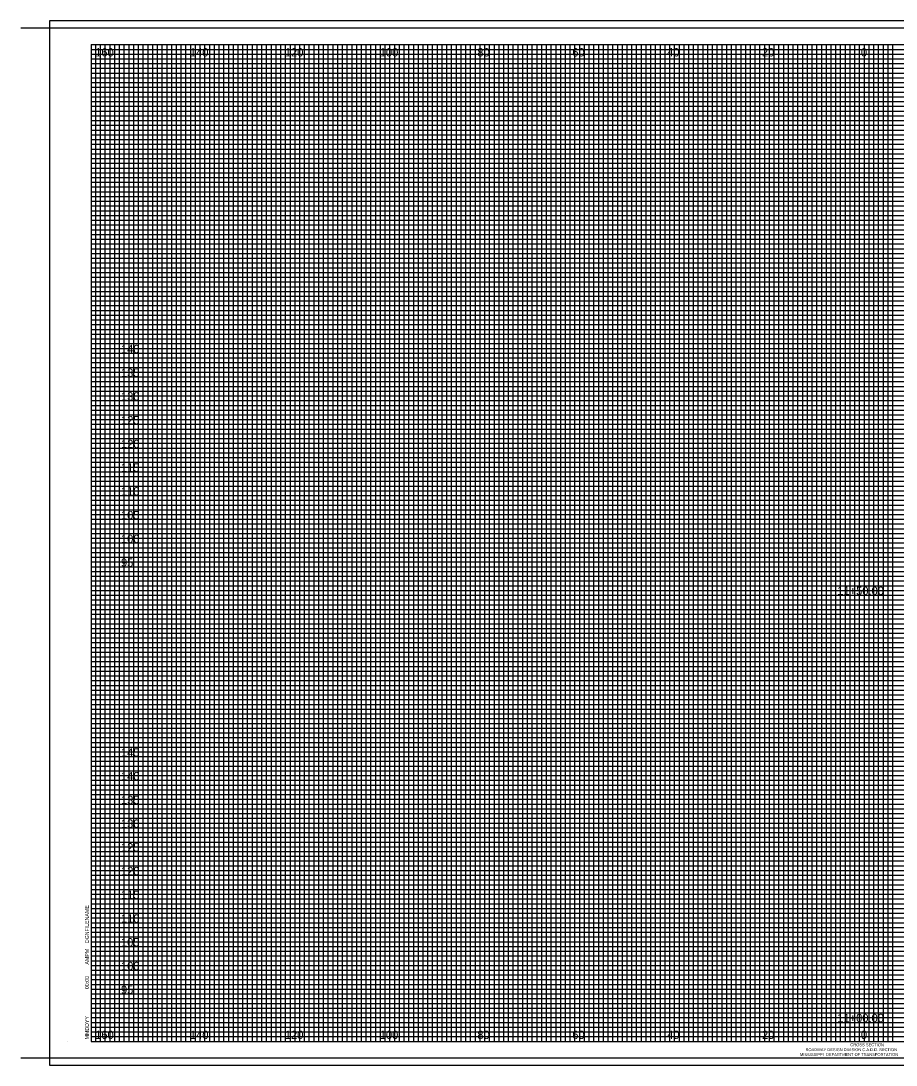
# Model space of a CAD drawing. Extents: x 21281 to 21817, y 6470 to 8300.
# Drawn here: x 21465 to 21649.5, y 6699.8 to 6919.8 of the extents above; entities that cross this region are included whole.
import ezdxf

# ---------------------------------------------------------------- set-up
doc = ezdxf.new("R2010")
doc.units = 0
for name, color, linetype in [('SHEET_BORDER', 7, 'Continuous'), ('SHEET_BORDER_TX', 7, 'Continuous'), ('SHEET_DATE_DGN_TX', 7, 'Continuous'), ('SHEET_PLOTTING_SHAPE', 7, 'Continuous'), ('XS_SHEET_LABELS_ELEVATION', 7, 'Continuous'), ('XS_SHEET_LABELS_OFFSET', 7, 'Continuous'), ('XS_SHEET_LABELS_STATION', 7, 'Continuous'), ('XS_SHEET_MAJOR_GRIDS', 7, 'Continuous'), ('XS_SHEET_MEDIUM_GRIDS', 7, 'Continuous'), ('XS_SHEET_MINOR_GRIDS', 7, 'Continuous')]:
    doc.layers.add(name, color=color, linetype=linetype)

msp = doc.modelspace()

# ---------------------------------------------------------------- linework, layer by layer
at = {"layer": 'SHEET_BORDER'}
for p, q in [((21465.04, 6918.34), (21817.04, 6918.34)), ((21479.84, 6914.84), (21814.84, 6914.84)), ((21479.84, 6914.84), (21479.84, 6704.84)), ((21623.84, 6704.84), (21623.84, 6914.84)), ((21474.84, 6704.84), (21474.84, 6704.84)), ((21479.84, 6704.84), (21814.84, 6704.84)), ((21465.04, 6701.34), (21817.04, 6701.34))]:
    msp.add_line(p, q, dxfattribs=at)
at = {"layer": 'SHEET_PLOTTING_SHAPE'}
msp.add_lwpolyline([(21471.04, 6699.84), (21817.04, 6699.84), (21817.04, 6919.84), (21471.04, 6919.84)], close=True, dxfattribs=at)
at = {"layer": 'XS_SHEET_MAJOR_GRIDS'}
for p, q in [((21484.84, 6704.84), (21484.84, 6914.84)), ((21494.84, 6704.84), (21494.84, 6914.84)), ((21504.84, 6704.84), (21504.84, 6914.84)), ((21514.84, 6704.84), (21514.84, 6914.84)), ((21524.84, 6704.84), (21524.84, 6914.84)), ((21534.84, 6704.84), (21534.84, 6914.84)), ((21544.84, 6704.84), (21544.84, 6914.84)), ((21554.84, 6704.84), (21554.84, 6914.84)), ((21564.84, 6704.84), (21564.84, 6914.84)), ((21574.84, 6704.84), (21574.84, 6914.84)), ((21584.84, 6704.84), (21584.84, 6914.84)), ((21594.84, 6704.84), (21594.84, 6914.84)), ((21604.84, 6704.84), (21604.84, 6914.84)), ((21614.84, 6704.84), (21614.84, 6914.84)), ((21624.84, 6704.84), (21624.84, 6914.84)), ((21634.84, 6704.84), (21634.84, 6914.84)), ((21644.84, 6704.84), (21644.84, 6914.84)), ((21479.84, 6904.84), (21814.84, 6904.84)), ((21479.84, 6894.84), (21814.84, 6894.84)), ((21479.84, 6884.84), (21814.84, 6884.84)), ((21479.84, 6874.84), (21814.84, 6874.84)), ((21479.84, 6864.84), (21814.84, 6864.84)), ((21479.84, 6854.84), (21814.84, 6854.84)), ((21479.84, 6844.84), (21814.84, 6844.84)), ((21479.84, 6834.84), (21814.84, 6834.84)), ((21479.84, 6824.84), (21814.84, 6824.84)), ((21479.84, 6814.84), (21814.84, 6814.84)), ((21479.84, 6804.84), (21814.84, 6804.84)), ((21479.84, 6794.84), (21814.84, 6794.84)), ((21479.84, 6784.84), (21814.84, 6784.84)), ((21479.84, 6774.84), (21814.84, 6774.84)), ((21479.84, 6764.84), (21814.84, 6764.84)), ((21479.84, 6754.84), (21814.84, 6754.84)), ((21479.84, 6744.84), (21814.84, 6744.84)), ((21479.84, 6734.84), (21814.84, 6734.84)), ((21479.84, 6724.84), (21814.84, 6724.84)), ((21479.84, 6714.84), (21814.84, 6714.84))]:
    msp.add_line(p, q, dxfattribs=at)
at = {"layer": 'XS_SHEET_MEDIUM_GRIDS'}
for p, q in [((21489.84, 6704.84), (21489.84, 6914.84)), ((21499.84, 6704.84), (21499.84, 6914.84)), ((21509.84, 6704.84), (21509.84, 6914.84)), ((21519.84, 6704.84), (21519.84, 6914.84)), ((21529.84, 6704.84), (21529.84, 6914.84)), ((21539.84, 6704.84), (21539.84, 6914.84)), ((21549.84, 6704.84), (21549.84, 6914.84)), ((21559.84, 6704.84), (21559.84, 6914.84)), ((21569.84, 6704.84), (21569.84, 6914.84)), ((21579.84, 6704.84), (21579.84, 6914.84)), ((21589.84, 6704.84), (21589.84, 6914.84)), ((21599.84, 6704.84), (21599.84, 6914.84)), ((21609.84, 6704.84), (21609.84, 6914.84)), ((21619.84, 6704.84), (21619.84, 6914.84)), ((21629.84, 6704.84), (21629.84, 6914.84)), ((21639.84, 6704.84), (21639.84, 6914.84)), ((21479.84, 6909.84), (21787.84, 6909.84)), ((21479.84, 6899.84), (21814.84, 6899.84)), ((21479.84, 6889.84), (21814.84, 6889.84)), ((21479.84, 6879.84), (21814.84, 6879.84)), ((21479.84, 6869.84), (21814.84, 6869.84)), ((21479.84, 6859.84), (21814.84, 6859.84)), ((21479.84, 6849.84), (21814.84, 6849.84)), ((21479.84, 6839.84), (21814.84, 6839.84)), ((21479.84, 6829.84), (21814.84, 6829.84)), ((21479.84, 6819.84), (21814.84, 6819.84)), ((21479.84, 6809.84), (21814.84, 6809.84)), ((21479.84, 6799.84), (21814.84, 6799.84)), ((21479.84, 6789.84), (21814.84, 6789.84)), ((21479.84, 6779.84), (21814.84, 6779.84)), ((21479.84, 6769.84), (21814.84, 6769.84)), ((21479.84, 6759.84), (21814.84, 6759.84)), ((21479.84, 6749.84), (21814.84, 6749.84)), ((21479.84, 6739.84), (21814.84, 6739.84)), ((21479.84, 6729.84), (21814.84, 6729.84)), ((21479.84, 6719.84), (21814.84, 6719.84)), ((21479.84, 6709.84), (21804.84, 6709.84))]:
    msp.add_line(p, q, dxfattribs=at)
at = {"layer": 'XS_SHEET_MINOR_GRIDS'}
for p, q in [((21480.84, 6704.84), (21480.84, 6914.84)), ((21481.84, 6704.84), (21481.84, 6914.84)), ((21482.84, 6704.84), (21482.84, 6914.84)), ((21483.84, 6704.84), (21483.84, 6914.84)), ((21485.84, 6704.84), (21485.84, 6914.84)), ((21486.84, 6704.84), (21486.84, 6914.84)), ((21487.84, 6704.84), (21487.84, 6914.84)), ((21488.84, 6704.84), (21488.84, 6914.84)), ((21490.84, 6704.84), (21490.84, 6914.84)), ((21491.84, 6704.84), (21491.84, 6914.84)), ((21492.84, 6704.84), (21492.84, 6914.84)), ((21493.84, 6704.84), (21493.84, 6914.84)), ((21495.84, 6704.84), (21495.84, 6914.84)), ((21496.84, 6704.84), (21496.84, 6914.84)), ((21497.84, 6704.84), (21497.84, 6914.84)), ((21498.84, 6704.84), (21498.84, 6914.84)), ((21500.84, 6704.84), (21500.84, 6914.84)), ((21501.84, 6704.84), (21501.84, 6914.84)), ((21502.84, 6704.84), (21502.84, 6914.84)), ((21503.84, 6704.84), (21503.84, 6914.84)), ((21505.84, 6704.84), (21505.84, 6914.84)), ((21506.84, 6704.84), (21506.84, 6914.84)), ((21507.84, 6704.84), (21507.84, 6914.84)), ((21508.84, 6704.84), (21508.84, 6914.84)), ((21510.84, 6704.84), (21510.84, 6914.84)), ((21511.84, 6704.84), (21511.84, 6914.84)), ((21512.84, 6704.84), (21512.84, 6914.84)), ((21513.84, 6704.84), (21513.84, 6914.84)), ((21515.84, 6704.84), (21515.84, 6914.84)), ((21516.84, 6704.84), (21516.84, 6914.84)), ((21517.84, 6704.84), (21517.84, 6914.84)), ((21518.84, 6704.84), (21518.84, 6914.84)), ((21520.84, 6704.84), (21520.84, 6914.84)), ((21521.84, 6704.84), (21521.84, 6914.84)), ((21522.84, 6704.84), (21522.84, 6914.84)), ((21523.84, 6704.84), (21523.84, 6914.84)), ((21525.84, 6704.84), (21525.84, 6914.84)), ((21526.84, 6704.84), (21526.84, 6914.84)), ((21527.84, 6704.84), (21527.84, 6914.84)), ((21528.84, 6704.84), (21528.84, 6914.84)), ((21530.84, 6704.84), (21530.84, 6914.84)), ((21531.84, 6704.84), (21531.84, 6914.84)), ((21532.84, 6704.84), (21532.84, 6914.84)), ((21533.84, 6704.84), (21533.84, 6914.84)), ((21535.84, 6704.84), (21535.84, 6914.84)), ((21536.84, 6704.84), (21536.84, 6914.84)), ((21537.84, 6704.84), (21537.84, 6914.84)), ((21538.84, 6704.84), (21538.84, 6914.84)), ((21540.84, 6704.84), (21540.84, 6914.84)), ((21541.84, 6704.84), (21541.84, 6914.84)), ((21542.84, 6704.84), (21542.84, 6914.84)), ((21543.84, 6704.84), (21543.84, 6914.84)), ((21545.84, 6704.84), (21545.84, 6914.84)), ((21546.84, 6704.84), (21546.84, 6914.84)), ((21547.84, 6704.84), (21547.84, 6914.84)), ((21548.84, 6704.84), (21548.84, 6914.84)), ((21550.84, 6704.84), (21550.84, 6914.84)), ((21551.84, 6704.84), (21551.84, 6914.84)), ((21552.84, 6704.84), (21552.84, 6914.84)), ((21553.84, 6704.84), (21553.84, 6914.84)), ((21555.84, 6704.84), (21555.84, 6914.84)), ((21556.84, 6704.84), (21556.84, 6914.84)), ((21557.84, 6704.84), (21557.84, 6914.84)), ((21558.84, 6704.84), (21558.84, 6914.84)), ((21560.84, 6704.84), (21560.84, 6914.84)), ((21561.84, 6704.84), (21561.84, 6914.84)), ((21562.84, 6704.84), (21562.84, 6914.84)), ((21563.84, 6704.84), (21563.84, 6914.84)), ((21565.84, 6704.84), (21565.84, 6914.84)), ((21566.84, 6704.84), (21566.84, 6914.84)), ((21567.84, 6704.84), (21567.84, 6914.84)), ((21568.84, 6704.84), (21568.84, 6914.84)), ((21570.84, 6704.84), (21570.84, 6914.84)), ((21571.84, 6704.84), (21571.84, 6914.84)), ((21572.84, 6704.84), (21572.84, 6914.84)), ((21573.84, 6704.84), (21573.84, 6914.84)), ((21575.84, 6704.84), (21575.84, 6914.84)), ((21576.84, 6704.84), (21576.84, 6914.84)), ((21577.84, 6704.84), (21577.84, 6914.84)), ((21578.84, 6704.84), (21578.84, 6914.84)), ((21580.84, 6704.84), (21580.84, 6914.84)), ((21581.84, 6704.84), (21581.84, 6914.84)), ((21582.84, 6704.84), (21582.84, 6914.84)), ((21583.84, 6704.84), (21583.84, 6914.84)), ((21585.84, 6704.84), (21585.84, 6914.84)), ((21586.84, 6704.84), (21586.84, 6914.84)), ((21587.84, 6704.84), (21587.84, 6914.84)), ((21588.84, 6704.84), (21588.84, 6914.84)), ((21590.84, 6704.84), (21590.84, 6914.84)), ((21591.84, 6704.84), (21591.84, 6914.84)), ((21592.84, 6704.84), (21592.84, 6914.84)), ((21593.84, 6704.84), (21593.84, 6914.84)), ((21595.84, 6704.84), (21595.84, 6914.84)), ((21596.84, 6704.84), (21596.84, 6914.84)), ((21597.84, 6704.84), (21597.84, 6914.84)), ((21598.84, 6704.84), (21598.84, 6914.84)), ((21600.84, 6704.84), (21600.84, 6914.84)), ((21601.84, 6704.84), (21601.84, 6914.84)), ((21602.84, 6704.84), (21602.84, 6914.84)), ((21603.84, 6704.84), (21603.84, 6914.84)), ((21605.84, 6704.84), (21605.84, 6914.84)), ((21606.84, 6704.84), (21606.84, 6914.84)), ((21607.84, 6704.84), (21607.84, 6914.84)), ((21608.84, 6704.84), (21608.84, 6914.84)), ((21610.84, 6704.84), (21610.84, 6914.84)), ((21611.84, 6704.84), (21611.84, 6914.84)), ((21612.84, 6704.84), (21612.84, 6914.84)), ((21613.84, 6704.84), (21613.84, 6914.84)), ((21615.84, 6704.84), (21615.84, 6914.84)), ((21616.84, 6704.84), (21616.84, 6914.84)), ((21617.84, 6704.84), (21617.84, 6914.84)), ((21618.84, 6704.84), (21618.84, 6914.84)), ((21620.84, 6704.84), (21620.84, 6914.84)), ((21621.84, 6704.84), (21621.84, 6914.84)), ((21622.84, 6704.84), (21622.84, 6914.84)), ((21625.84, 6704.84), (21625.84, 6914.84)), ((21626.84, 6704.84), (21626.84, 6914.84)), ((21627.84, 6704.84), (21627.84, 6914.84)), ((21628.84, 6704.84), (21628.84, 6914.84)), ((21630.84, 6704.84), (21630.84, 6914.84)), ((21631.84, 6704.84), (21631.84, 6914.84)), ((21632.84, 6704.84), (21632.84, 6914.84)), ((21633.84, 6704.84), (21633.84, 6914.84)), ((21635.84, 6704.84), (21635.84, 6914.84)), ((21636.84, 6704.84), (21636.84, 6914.84)), ((21637.84, 6704.84), (21637.84, 6914.84)), ((21638.84, 6704.84), (21638.84, 6914.84)), ((21640.84, 6704.84), (21640.84, 6914.84)), ((21641.84, 6704.84), (21641.84, 6914.84)), ((21642.84, 6704.84), (21642.84, 6914.84)), ((21643.84, 6704.84), (21643.84, 6914.84)), ((21645.84, 6704.84), (21645.84, 6914.84)), ((21646.84, 6704.84), (21646.84, 6914.84)), ((21647.84, 6704.84), (21647.84, 6914.84)), ((21648.84, 6704.84), (21648.84, 6914.84)), ((21479.84, 6913.84), (21787.84, 6913.84)), ((21479.84, 6912.84), (21787.84, 6912.84)), ((21479.84, 6911.84), (21787.84, 6911.84)), ((21479.84, 6910.84), (21787.84, 6910.84)), ((21479.84, 6908.84), (21787.84, 6908.84)), ((21479.84, 6907.84), (21787.84, 6907.84)), ((21479.84, 6906.84), (21787.84, 6906.84)), ((21479.84, 6905.84), (21814.84, 6905.84)), ((21479.84, 6903.84), (21814.84, 6903.84)), ((21479.84, 6902.84), (21814.84, 6902.84)), ((21479.84, 6901.84), (21814.84, 6901.84)), ((21479.84, 6900.84), (21814.84, 6900.84)), ((21479.84, 6898.84), (21814.84, 6898.84)), ((21479.84, 6897.84), (21814.84, 6897.84)), ((21479.84, 6896.84), (21814.84, 6896.84)), ((21479.84, 6895.84), (21814.84, 6895.84)), ((21479.84, 6893.84), (21814.84, 6893.84)), ((21479.84, 6892.84), (21814.84, 6892.84)), ((21479.84, 6891.84), (21814.84, 6891.84)), ((21479.84, 6890.84), (21814.84, 6890.84)), ((21479.84, 6888.84), (21814.84, 6888.84)), ((21479.84, 6887.84), (21814.84, 6887.84)), ((21479.84, 6886.84), (21814.84, 6886.84)), ((21479.84, 6885.84), (21814.84, 6885.84)), ((21479.84, 6883.84), (21814.84, 6883.84)), ((21479.84, 6882.84), (21814.84, 6882.84)), ((21479.84, 6881.84), (21814.84, 6881.84)), ((21479.84, 6880.84), (21814.84, 6880.84)), ((21479.84, 6878.84), (21814.84, 6878.84)), ((21479.84, 6877.84), (21814.84, 6877.84)), ((21479.84, 6876.84), (21814.84, 6876.84)), ((21479.84, 6875.84), (21814.84, 6875.84)), ((21479.84, 6873.84), (21814.84, 6873.84)), ((21479.84, 6872.84), (21814.84, 6872.84)), ((21479.84, 6871.84), (21814.84, 6871.84)), ((21479.84, 6870.84), (21814.84, 6870.84)), ((21479.84, 6868.84), (21814.84, 6868.84)), ((21479.84, 6867.84), (21814.84, 6867.84)), ((21479.84, 6866.84), (21814.84, 6866.84)), ((21479.84, 6865.84), (21814.84, 6865.84)), ((21479.84, 6863.84), (21814.84, 6863.84)), ((21479.84, 6862.84), (21814.84, 6862.84)), ((21479.84, 6861.84), (21814.84, 6861.84)), ((21479.84, 6860.84), (21814.84, 6860.84)), ((21479.84, 6858.84), (21814.84, 6858.84)), ((21479.84, 6857.84), (21814.84, 6857.84)), ((21479.84, 6856.84), (21814.84, 6856.84)), ((21479.84, 6855.84), (21814.84, 6855.84)), ((21479.84, 6853.84), (21814.84, 6853.84)), ((21479.84, 6852.84), (21814.84, 6852.84)), ((21479.84, 6851.84), (21814.84, 6851.84)), ((21479.84, 6850.84), (21814.84, 6850.84)), ((21479.84, 6848.84), (21814.84, 6848.84)), ((21479.84, 6847.84), (21814.84, 6847.84)), ((21479.84, 6846.84), (21814.84, 6846.84)), ((21479.84, 6845.84), (21814.84, 6845.84)), ((21479.84, 6843.84), (21814.84, 6843.84)), ((21479.84, 6842.84), (21814.84, 6842.84)), ((21479.84, 6841.84), (21814.84, 6841.84)), ((21479.84, 6840.84), (21814.84, 6840.84)), ((21479.84, 6838.84), (21814.84, 6838.84)), ((21479.84, 6837.84), (21814.84, 6837.84)), ((21479.84, 6836.84), (21814.84, 6836.84)), ((21479.84, 6835.84), (21814.84, 6835.84)), ((21479.84, 6833.84), (21814.84, 6833.84)), ((21479.84, 6832.84), (21814.84, 6832.84)), ((21479.84, 6831.84), (21814.84, 6831.84)), ((21479.84, 6830.84), (21814.84, 6830.84)), ((21479.84, 6828.84), (21814.84, 6828.84)), ((21479.84, 6827.84), (21814.84, 6827.84)), ((21479.84, 6826.84), (21814.84, 6826.84)), ((21479.84, 6825.84), (21814.84, 6825.84)), ((21479.84, 6823.84), (21814.84, 6823.84)), ((21479.84, 6822.84), (21814.84, 6822.84)), ((21479.84, 6821.84), (21814.84, 6821.84)), ((21479.84, 6820.84), (21814.84, 6820.84)), ((21479.84, 6818.84), (21814.84, 6818.84)), ((21479.84, 6817.84), (21814.84, 6817.84)), ((21479.84, 6816.84), (21814.84, 6816.84)), ((21479.84, 6815.84), (21814.84, 6815.84)), ((21479.84, 6813.84), (21814.84, 6813.84)), ((21479.84, 6812.84), (21814.84, 6812.84)), ((21479.84, 6811.84), (21814.84, 6811.84)), ((21479.84, 6810.84), (21814.84, 6810.84)), ((21479.84, 6808.84), (21814.84, 6808.84)), ((21479.84, 6807.84), (21814.84, 6807.84)), ((21479.84, 6806.84), (21814.84, 6806.84)), ((21479.84, 6805.84), (21814.84, 6805.84)), ((21479.84, 6803.84), (21814.84, 6803.84)), ((21479.84, 6802.84), (21814.84, 6802.84)), ((21479.84, 6801.84), (21814.84, 6801.84)), ((21479.84, 6800.84), (21814.84, 6800.84)), ((21479.84, 6798.84), (21814.84, 6798.84)), ((21479.84, 6797.84), (21814.84, 6797.84)), ((21479.84, 6796.84), (21814.84, 6796.84)), ((21479.84, 6795.84), (21814.84, 6795.84)), ((21479.84, 6793.84), (21814.84, 6793.84)), ((21479.84, 6792.84), (21814.84, 6792.84)), ((21479.84, 6791.84), (21814.84, 6791.84)), ((21479.84, 6790.84), (21814.84, 6790.84)), ((21479.84, 6788.84), (21814.84, 6788.84)), ((21479.84, 6787.84), (21814.84, 6787.84)), ((21479.84, 6786.84), (21814.84, 6786.84)), ((21479.84, 6785.84), (21814.84, 6785.84)), ((21479.84, 6783.84), (21814.84, 6783.84)), ((21479.84, 6782.84), (21814.84, 6782.84)), ((21479.84, 6781.84), (21814.84, 6781.84)), ((21479.84, 6780.84), (21814.84, 6780.84)), ((21479.84, 6778.84), (21814.84, 6778.84)), ((21479.84, 6777.84), (21814.84, 6777.84)), ((21479.84, 6776.84), (21814.84, 6776.84)), ((21479.84, 6775.84), (21814.84, 6775.84)), ((21479.84, 6773.84), (21814.84, 6773.84)), ((21479.84, 6772.84), (21814.84, 6772.84)), ((21479.84, 6771.84), (21814.84, 6771.84)), ((21479.84, 6770.84), (21814.84, 6770.84)), ((21479.84, 6768.84), (21814.84, 6768.84)), ((21479.84, 6767.84), (21814.84, 6767.84)), ((21479.84, 6766.84), (21814.84, 6766.84)), ((21479.84, 6765.84), (21814.84, 6765.84)), ((21479.84, 6763.84), (21814.84, 6763.84)), ((21479.84, 6762.84), (21814.84, 6762.84)), ((21479.84, 6761.84), (21814.84, 6761.84)), ((21479.84, 6760.84), (21814.84, 6760.84)), ((21479.84, 6758.84), (21814.84, 6758.84)), ((21479.84, 6757.84), (21814.84, 6757.84)), ((21479.84, 6756.84), (21814.84, 6756.84)), ((21479.84, 6755.84), (21814.84, 6755.84)), ((21479.84, 6753.84), (21814.84, 6753.84)), ((21479.84, 6752.84), (21814.84, 6752.84)), ((21479.84, 6751.84), (21814.84, 6751.84)), ((21479.84, 6750.84), (21814.84, 6750.84)), ((21479.84, 6748.84), (21814.84, 6748.84)), ((21479.84, 6747.84), (21814.84, 6747.84)), ((21479.84, 6746.84), (21814.84, 6746.84)), ((21479.84, 6745.84), (21814.84, 6745.84)), ((21479.84, 6743.84), (21814.84, 6743.84)), ((21479.84, 6742.84), (21814.84, 6742.84)), ((21479.84, 6741.84), (21814.84, 6741.84)), ((21479.84, 6740.84), (21814.84, 6740.84)), ((21479.84, 6738.84), (21814.84, 6738.84)), ((21479.84, 6737.84), (21814.84, 6737.84)), ((21479.84, 6736.84), (21814.84, 6736.84)), ((21479.84, 6735.84), (21814.84, 6735.84)), ((21479.84, 6733.84), (21814.84, 6733.84)), ((21479.84, 6732.84), (21814.84, 6732.84)), ((21479.84, 6731.84), (21814.84, 6731.84)), ((21479.84, 6730.84), (21814.84, 6730.84)), ((21479.84, 6728.84), (21814.84, 6728.84)), ((21479.84, 6727.84), (21814.84, 6727.84)), ((21479.84, 6726.84), (21814.84, 6726.84)), ((21479.84, 6725.84), (21814.84, 6725.84)), ((21479.84, 6725.84), (21814.84, 6725.84)), ((21479.84, 6725.84), (21814.84, 6725.84)), ((21479.84, 6723.84), (21814.84, 6723.84)), ((21479.84, 6722.84), (21814.84, 6722.84)), ((21479.84, 6721.84), (21814.84, 6721.84)), ((21479.84, 6720.84), (21814.84, 6720.84)), ((21479.84, 6718.84), (21814.84, 6718.84)), ((21479.84, 6717.84), (21814.84, 6717.84)), ((21479.84, 6716.84), (21814.84, 6716.84)), ((21479.84, 6715.84), (21814.84, 6715.84)), ((21479.84, 6713.84), (21804.84, 6713.84)), ((21479.84, 6712.84), (21804.84, 6712.84)), ((21479.84, 6711.84), (21804.84, 6711.84)), ((21479.84, 6710.84), (21804.84, 6710.84)), ((21479.84, 6710.84), (21804.84, 6710.84)), ((21479.84, 6710.84), (21804.84, 6710.84)), ((21479.84, 6708.84), (21804.84, 6708.84)), ((21479.84, 6707.84), (21804.84, 6707.84)), ((21479.84, 6706.84), (21804.84, 6706.84)), ((21479.84, 6705.84), (21804.84, 6705.84))]:
    msp.add_line(p, q, dxfattribs=at)

# ---------------------------------------------------------------- texts
at = {"layer": 'SHEET_BORDER_TX'}
for s, height, p in [('ROADWAY DESIGN DIVISION C.A.D.D. SECTION', 0.61, (21630.44, 6702.78)), ('CROSS SECTION', 0.62, (21639.87, 6703.81)), ('MISSISSIPPI  DEPARTMENT OF TRANSPORTATION', 0.61, (21629.27, 6701.75))]:
    msp.add_text(s, height=height, dxfattribs=at).set_placement(p)
at = {"layer": 'SHEET_DATE_DGN_TX'}
for s, p in [('DGNFILENAME', (21479.37, 6725.54)), ('AMPM', (21479.37, 6721.02)), ('00:00', (21479.37, 6715.84)), ('MMDDYY', (21479.37, 6705.26))]:
    msp.add_text(s, height=0.8, rotation=90, dxfattribs=at).set_placement(p)
at = {"layer": 'XS_SHEET_LABELS_ELEVATION'}
for s, p in [('  140  ', (21484.84, 6849.84)), ('  135  ', (21484.84, 6844.84)), ('  130  ', (21484.84, 6839.84)), ('  125  ', (21484.84, 6834.84)), ('  120  ', (21484.84, 6829.84)), ('  115  ', (21484.84, 6824.84)), ('  110  ', (21484.84, 6819.84)), ('  105  ', (21484.84, 6814.84)), ('  100  ', (21484.84, 6809.84)), ('  95  ', (21484.84, 6804.84)), ('  145  ', (21484.84, 6764.84)), ('  140  ', (21484.84, 6759.84)), ('  135  ', (21484.84, 6754.84)), ('  130  ', (21484.84, 6749.84)), ('  125  ', (21484.84, 6744.84)), ('  120  ', (21484.84, 6739.84)), ('  115  ', (21484.84, 6734.84)), ('  110  ', (21484.84, 6729.84)), ('  105  ', (21484.84, 6724.84)), ('  100  ', (21484.84, 6719.84)), ('  95  ', (21484.84, 6714.84))]:
    msp.add_text(s, height=1.75, dxfattribs=at).set_placement(p)
at = {"layer": 'XS_SHEET_LABELS_OFFSET'}
for s, p in [('  160  ', (21479.4, 6912.34)), ('  140  ', (21499.39, 6912.34)), ('  120  ', (21519.39, 6912.34)), ('  100  ', (21539.39, 6912.34)), ('  80  ', (21559.95, 6912.34)), ('  60  ', (21579.97, 6912.34)), ('  40  ', (21599.95, 6912.34)), ('  20  ', (21619.95, 6912.34)), ('  0  ', (21640.81, 6912.34)), ('  0  ', (21640.81, 6912.34)), ('  160  ', (21479.4, 6705.34)), ('  140  ', (21499.39, 6705.34)), ('  120  ', (21519.39, 6705.34)), ('  100  ', (21539.39, 6705.34)), ('  80  ', (21559.95, 6705.34)), ('  60  ', (21579.97, 6705.34)), ('  40  ', (21599.95, 6705.34)), ('  20  ', (21619.95, 6705.34)), ('  0  ', (21640.81, 6705.34)), ('  0  ', (21640.81, 6705.34))]:
    msp.add_text(s, height=1.75, dxfattribs=at).set_placement(p)
at = {"layer": 'XS_SHEET_LABELS_STATION'}
for s, p in [('  11+50.00  ', (21635.83, 6798.89)), ('  11+00.00  ', (21635.83, 6708.89))]:
    msp.add_text(s, height=1.75, dxfattribs=at).set_placement(p)

doc.saveas('drawing.dxf')
